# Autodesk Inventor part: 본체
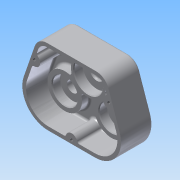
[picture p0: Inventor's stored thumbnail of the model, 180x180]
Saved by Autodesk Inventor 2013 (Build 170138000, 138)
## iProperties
Created: 2014-12
Part Number: 본체
Material: 알루미늄 6061
Document SubType Name: Modeling
Designer: Administrator
Density: 2.71 g/cm^3
Mass: 614.084 g
Surface Area: 665.346 cm^2
Volume: 226.599 cm^3
Author: Administrator
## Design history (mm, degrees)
sketch "스케치1"
  geometry: L1 (-34.162, 36)-(34.162, 36); L2 (-32.527, -68.527)-(32.527, -68.527); L3 (-66.565, -20.803)-(-51.181, 23.862); L4 (66.565, -20.803)-(51.181, 23.862); A1 r 36 centre (-32.527, -32.527) between (-66.565, -20.803) and (-32.527, -68.527) reference; A2 r 36 centre (32.527, -32.527) between (32.527, -68.527) and (66.565, -20.803) reference; A3 r 18 centre (-34.162, 18) between (-34.162, 36) and (-51.181, 23.862); A4 r 18 centre (34.162, 18) between (51.181, 23.862) and (34.162, 36); 3 further points
  constraints: 8 end point, 8 point on circle, 7 tangent, 4 centre point, 4 point on line, 1 equal radius, 2 other
extrude "돌출1" new body sketch "스케치1" distance "d10" = 10; taper "d11" = 0 deg
sketch "스케치2"
  geometry: L1 (66.565, -20.803)-(51.181, 23.862) reference; L2 (34.162, 36)-(-34.162, 36) reference; L3 (-51.181, 23.862)-(-66.565, -20.803) reference; L4 (-32.527, -68.527)-(32.527, -68.527) reference; L5 (-34.162, 31)-(34.162, 31); L6 (-61.837, -22.432)-(-54.305, -0.564); L7 (-49.095, 14.564)-(-46.453, 22.233); L8 (46.453, 22.233)-(49.095, 14.564); L9 (54.305, -0.564)-(61.837, -22.432); L10 (32.527, -63.527)-(8, -63.527); L11 (-8, -63.527)-(-32.527, -63.527); A1 r 18 centre (34.162, 18) between (51.181, 23.862) and (34.162, 36) reference; A2 r 18 centre (-34.162, 18) between (-34.162, 36) and (-51.181, 23.862) reference; A3 r 36 centre (-32.527, -32.527) between (-66.565, -20.803) and (-32.527, -68.527) reference; A4 r 36 centre (32.527, -32.527) between (32.527, -68.527) and (66.565, -20.803) reference; A5 r 13 centre (34.162, 18) between (46.453, 22.233) and (34.162, 31); A6 r 31 centre (32.527, -32.527) between (32.527, -63.527) and (61.837, -22.432); A7 r 31 centre (-32.527, -32.527) between (-61.837, -22.432) and (-32.527, -63.527); A8 r 13 centre (-34.162, 18) between (-34.162, 31) and (-46.453, 22.233); A9 r 8 centre (51.7, 7) between (49.095, 14.564) and (54.305, -0.564); A10 r 8 centre (0, -63.527) between (8, -63.527) and (-8, -63.527); A11 r 8 centre (-51.7, 7) between (-54.305, -0.564) and (-49.095, 14.564)
  constraints: 14 end point, 14 point on circle, 7 centre point, 1 other
extrude "돌출2" join sketch "스케치2" distance "d17" = 34; taper "d18" = 0 deg
sketch "스케치3"
  geometry: L1 (34.162, 31)-(-34.162, 31) reference; L2 (-46.453, 22.233)-(-49.095, 14.564) reference; L3 (-54.305, -0.564)-(-61.837, -22.432) reference; L4 (-32.527, -63.527)-(-8, -63.527) reference; L5 (8, -63.527)-(32.527, -63.527) reference; L6 (61.837, -22.432)-(54.305, -0.564) reference; L7 (49.095, 14.564)-(46.453, 22.233) reference; A1 r 13 centre (34.162, 18) between (46.453, 22.233) and (34.162, 31) reference; A2 r 13 centre (-34.162, 18) between (-34.162, 31) and (-46.453, 22.233) reference; A3 r 8 centre (-51.7, 7) between (-54.305, -0.564) and (-49.095, 14.564) reference; A4 r 31 centre (-32.527, -32.527) between (-61.837, -22.432) and (-32.527, -63.527) reference; A5 r 8 centre (0, -63.527) between (8, -63.527) and (-8, -63.527) reference; A6 r 31 centre (32.527, -32.527) between (32.527, -63.527) and (61.837, -22.432) reference; A7 r 8 centre (51.7, 7) between (49.095, 14.564) and (54.305, -0.564) reference; A8 r 24 centre (-32.527, -32.527) between (-26.959, -9.182) and (-9.182, -26.959); A9 r 24 centre (32.527, -32.527) between (9.182, -26.959) and (26.959, -9.182); A10 r 24 centre (0, 0) between (-5.568, -23.345) and (5.568, -23.345); A11 r 24 centre (0, 0) between (23.345, -5.568) and (-23.345, -5.568); A12 r 3 centre (-26.263, -6.263) between (-26.959, -9.182) and (-23.345, -5.568); A13 r 3 centre (-6.263, -26.263) between (-5.568, -23.345) and (-9.182, -26.959); A14 r 3 centre (6.263, -26.263) between (9.182, -26.959) and (5.568, -23.345); A15 r 3 centre (26.263, -6.263) between (23.345, -5.568) and (26.959, -9.182)
  constraints: 16 point on circle, 8 centre point, 8 tangent, 3 equal radius, 2 coincident
extrude "돌출3" join sketch "스케치3" distance "d40" = 11; taper "d41" = 0 deg
sketch "스케치4"
  geometry: C1 r 20 at (0, 0)
  constraints: 1 centre point
extrude "돌출4" cut sketch "스케치4" distance "d45" = 12; taper "d46" = 0 deg
sketch "스케치5"
  geometry: C1 r 10 at (0, 0); 1 further point
  constraints: 1 centre point, 1 coincident
extrude "돌출5" cut sketch "스케치5" distance "d48" = 3; taper "d49" = 0 deg
sketch "스케치6"
  geometry: C1 r 17.5 at (-32.527, -32.527); C2 r 17.5 at (32.527, -32.527)
  constraints: 2 centre point
extrude "돌출6" cut sketch "스케치6" distance "d52" = 11; taper "d53" = 0 deg
sketch "스케치7"
  geometry: C1 r 20 at (-32.527, 32.527); C2 r 20 at (32.527, 32.527)
  constraints: 2 centre point
extrude "돌출7" join sketch "스케치7" distance "d56" = 7; taper "d57" = -10 deg
sketch "스케치8"
  geometry: 3 further points
hole "구멍1" sketch "스케치8" at (-65.054, 0), (0, 0) diameter "d58" = 15.5; stored, may be unused: countersink angle "d62" = 90 deg, drill point angle "d64" = 118 deg; dims "d59" = 6, "d60" = 30, "d61" = 7, "d63" = 8
sketch "스케치9"
  geometry: 3 further points
hole "구멍2" sketch "스케치9" at (-51.7, 7), (51.7, 7), (0, -63.527) diameter "d65" = 4.134; stored, may be unused: countersink angle "d69" = 90 deg, drill point angle "d71" = 118 deg; dims "d66" = 20, "d67" = 30, "d68" = 7, "d70" = 23
sketch "스케치10"
  geometry: L1 (0, -36)-(0, -6); 1 further point
  constraints: 2 end point, 1 other
  dimensions: "d72" = 30 distance of L1.start L1.end
feature "엠보싱1" sketch "스케치10" dims "d74" = 1, "d75" = 0
chamfer "모따기1" distance "d76" = 1; stored, may be unused: second distance "d77" = 2, angle "d78" = 45 deg
chamfer "모따기2" distance "d79" = 1; stored, may be unused: second distance "d80" = 2, angle "d81" = 45 deg
chamfer "모따기3" distance "d82" = 1; stored, may be unused: second distance "d83" = 2, angle "d84" = 45 deg
chamfer "모따기4" distance "d85" = 1; stored, may be unused: second distance "d86" = 2, angle "d87" = 45 deg
chamfer "모따기5" distance "d88" = 1; stored, may be unused: second distance "d89" = 2, angle "d90" = 45 deg
fillet "모깎기1" dims "d91" = 0.3
fillet "모깎기2" dims "d92" = 0.1
fillet "모깎기3" dims "d93" = 3
node "솔리드1"
node "투영된 루프1"
node "투영된 루프2"
other parameters: "d33" = 8, "d36" = 48
